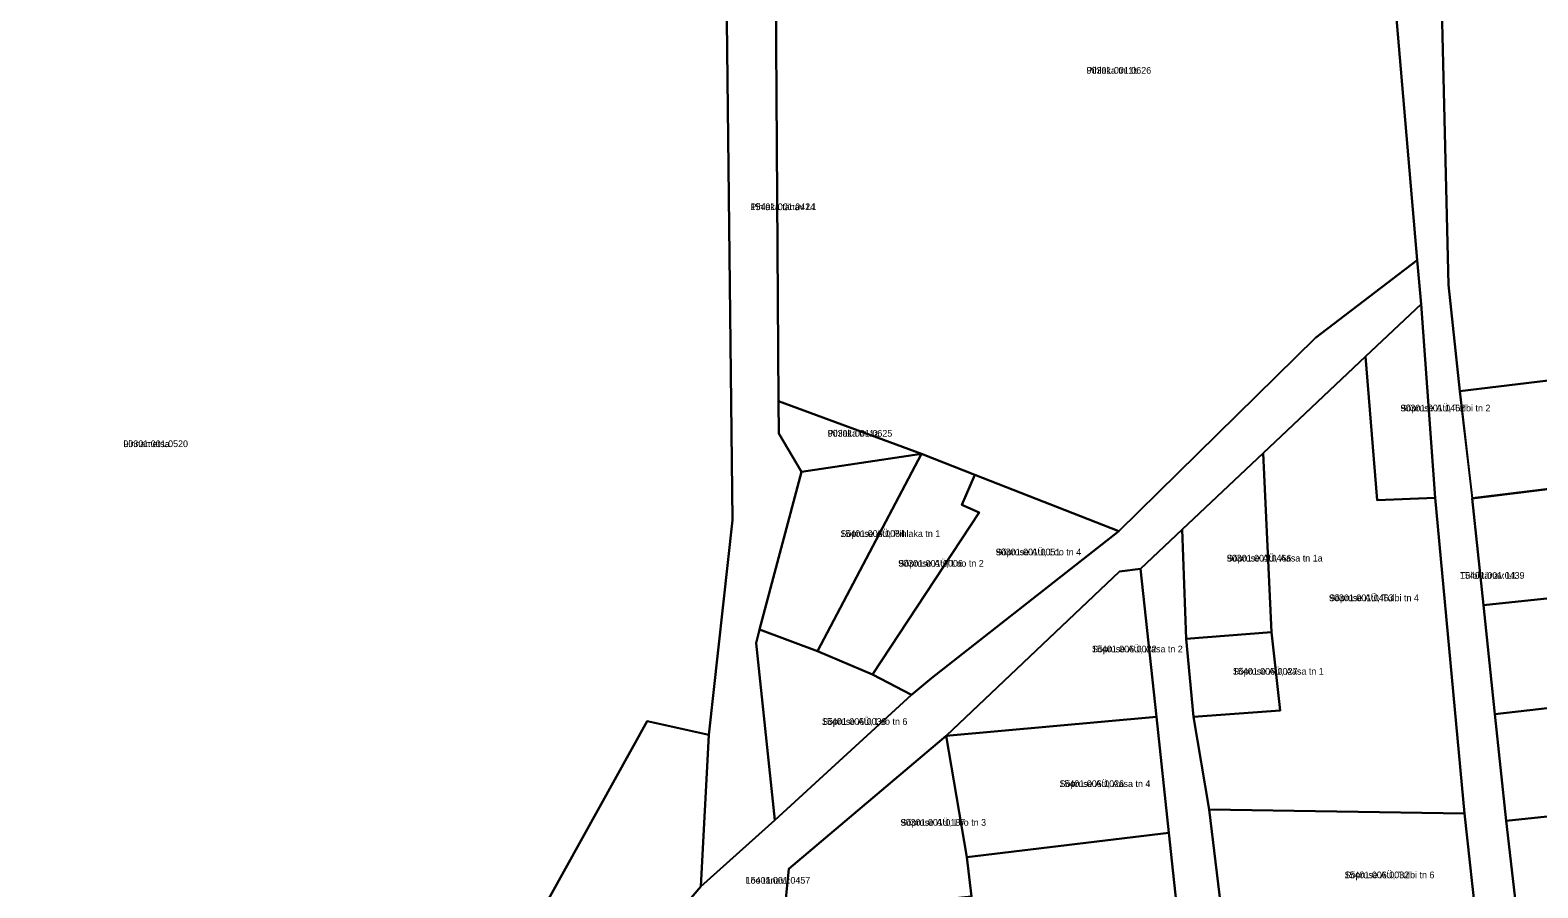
# Model space of a CAD drawing. Extents: x 634518 to 667988, y 6584667 to 6604739.
# Drawn here: x 662955.6 to 663294.1, y 6593480.9 to 6593673.3 of the extents above; entities that cross this region are included whole.
import ezdxf

# ---------------------------------------------------------------- set-up
doc = ezdxf.new("R2010")
doc.units = 0
for name, color, linetype in [('L_AADRESS', 7, 'Continuous'), ('PIIR', 7, 'Continuous'), ('TUNNUS', 7, 'Continuous')]:
    doc.layers.add(name, color=color, linetype=linetype)

msp = doc.modelspace()

# ---------------------------------------------------------------- linework, layer by layer
at = {"layer": 'PIIR'}
for points in [[(662942.12, 6593720.93), (662996.35, 6593723.15), (663060.31, 6593738.26), (663072.14, 6593752.95), (663052.3, 6593766.88), (663058.09, 6593774.85), (663073.35, 6593794.19), (663086.2, 6593810.49), (663094.98, 6593800.39), (663102.42, 6593789.23), (663105.9, 6593772.93), (663111.19, 6593748.06), (663113.31, 6593563.38), (663108.01, 6593515.2), (663094.14, 6593518.31), (663068.53, 6593472.17), (663061.55, 6593451.78), (663068.31, 6593436.61), (663032.81, 6593394.82), (662984.94, 6593349.08), (662885.24, 6593453.75)], [(663087.13, 6593458.83), (663106.19, 6593481.2), (663122.83, 6593496.08), (663153.48, 6593524.19), (663157.97, 6593527.94), (663200.02, 6593560.96), (663244.18, 6593604.26), (663267.01, 6593621.68), (663267.89, 6593611.85), (663255.42, 6593600.11), (663232.41, 6593578.44), (663214.22, 6593561.32), (663204.87, 6593552.51), (663200.17, 6593551.84), (663161.28, 6593514.98), (663125.91, 6593485.18), (663124.88, 6593474.7)], [(663213.68, 6593470.96), (663211.27, 6593493.24), (663208.45, 6593519.26), (663204.87, 6593552.51), (663214.22, 6593561.32), (663215.11, 6593536.77), (663216.81, 6593519.25), (663220.28, 6593498.49), (663224.04, 6593467.64)]]:
    msp.add_lwpolyline(points, dxfattribs=at)
for points in [[(663267.01, 6593621.68), (663244.18, 6593604.26), (663200.02, 6593560.96), (663167.68, 6593573.58), (663155.72, 6593578.26), (663123.65, 6593590.05), (663122.64, 6593738.81), (663118.55, 6593774.91), (663139.13, 6593779.62), (663155.42, 6593777.48), (663214.16, 6593755.18), (663244.18, 6593745.75), (663265.61, 6593735.03), (663262.35, 6593723.45), (663260.49, 6593707.97), (663261.89, 6593681.25)], [(663111.19, 6593748.06), (663105.9, 6593772.93), (663118.55, 6593774.91), (663122.64, 6593738.81), (663123.65, 6593590.05), (663123.7, 6593582.82), (663128.76, 6593574.2), (663119.33, 6593538.87), (663118.64, 6593535.8), (663122.83, 6593496.08), (663106.19, 6593481.2), (663108.01, 6593515.2), (663113.31, 6593563.38)], [(663265.61, 6593735.03), (663271.3, 6593730.99), (663274.02, 6593616.16), (663276.57, 6593592.3), (663279.38, 6593568.24), (663281.89, 6593544.35), (663284.45, 6593519.85), (663287, 6593495.93), (663289.83, 6593471.35), (663292.72, 6593445.68), (663281.81, 6593444.95), (663280.8, 6593454.14), (663280.56, 6593471), (663277.61, 6593497.59), (663271.07, 6593568.43), (663267.89, 6593611.85), (663267.01, 6593621.68), (663261.89, 6593681.25), (663260.49, 6593707.97), (663262.35, 6593723.45)], [(663274.02, 6593616.16), (663271.3, 6593730.99), (663308.03, 6593710.59), (663312.84, 6593638.75), (663317.48, 6593597.23), (663276.57, 6593592.3)], [(663267.89, 6593611.85), (663271.07, 6593568.43), (663258, 6593567.89), (663255.42, 6593600.11)], [(663255.42, 6593600.11), (663258, 6593567.89), (663271.07, 6593568.43), (663277.61, 6593497.59), (663220.28, 6593498.49), (663216.81, 6593519.25), (663236.26, 6593520.66), (663234.29, 6593538.24), (663232.41, 6593578.44)], [(663279.41, 6593568.36), (663276.57, 6593592.3), (663317.48, 6593597.23), (663319.87, 6593573.23)], [(663128.76, 6593574.2), (663123.7, 6593582.82), (663123.65, 6593590.05), (663155.72, 6593578.26)], [(663128.76, 6593574.2), (663155.72, 6593578.26), (663132.41, 6593534.04), (663119.33, 6593538.87)], [(663132.41, 6593534.04), (663155.72, 6593578.26), (663167.68, 6593573.58), (663164.75, 6593566.82), (663168.64, 6593565.08), (663144.76, 6593528.74)], [(663214.22, 6593561.32), (663232.41, 6593578.44), (663234.29, 6593538.24), (663215.11, 6593536.77)], [(663167.68, 6593573.58), (663200.02, 6593560.96), (663157.97, 6593527.94), (663153.48, 6593524.19), (663144.76, 6593528.74), (663168.64, 6593565.08), (663164.75, 6593566.82)], [(663281.89, 6593544.35), (663279.38, 6593568.24), (663319.87, 6593573.23), (663323.77, 6593548.72)], [(663200.17, 6593551.84), (663204.87, 6593552.51), (663208.45, 6593519.26), (663161.28, 6593514.98)], [(663323.77, 6593548.72), (663326.29, 6593524.63), (663284.45, 6593519.85), (663281.89, 6593544.35)], [(663119.33, 6593538.87), (663132.41, 6593534.04), (663144.76, 6593528.74), (663153.48, 6593524.19), (663122.83, 6593496.08), (663118.64, 6593535.8)], [(663215.11, 6593536.77), (663234.29, 6593538.24), (663236.26, 6593520.66), (663216.81, 6593519.25)], [(663284.45, 6593519.85), (663326.29, 6593524.63), (663328.84, 6593500.33), (663287, 6593495.93)], [(663068.53, 6593472.17), (663094.14, 6593518.31), (663108.01, 6593515.2), (663106.19, 6593481.2), (663087.13, 6593458.83), (663068.31, 6593436.61), (663061.55, 6593451.78)], [(663161.28, 6593514.98), (663208.45, 6593519.26), (663211.27, 6593493.24), (663165.91, 6593487.79)], [(663165.91, 6593487.79), (663166.96, 6593478.98), (663124.88, 6593474.7), (663125.91, 6593485.18), (663161.28, 6593514.98)], [(663328.84, 6593500.33), (663331.44, 6593475.5), (663289.83, 6593471.35), (663287, 6593495.93)], [(663224.04, 6593467.64), (663220.28, 6593498.49), (663277.61, 6593497.59), (663280.56, 6593471)], [(663165.91, 6593487.79), (663211.27, 6593493.24), (663213.68, 6593470.96), (663168.39, 6593464.38), (663166.96, 6593478.98)]]:
    msp.add_lwpolyline(points, close=True, dxfattribs=at)

# ---------------------------------------------------------------- texts
at = {"layer": 'L_AADRESS'}
for s, p in [('Pihlaka tn 1b', (663192.78, 6593663.54)), ('Pihlaka tänav L1', (663117.33, 6593632.94)), ('Sõpruse AÜ, Tulbi tn 2', (663263.25, 6593587.79)), ('Linnametsa', (662976.55, 6593579.78)), ('Pihlaka tn 1a', (663134.66, 6593582.12)), ('Sõpruse AÜ, Pihlaka tn 1', (663137.52, 6593559.63)), ('Sõpruse AÜ, Loo tn 4', (663172.39, 6593555.5)), ('Sõpruse AÜ, Loo tn 2', (663150.52, 6593552.96)), ('Sõpruse AÜ, Aasa tn 1a', (663224.25, 6593554.12)), ('Tulbi tänav L1', (663276.61, 6593550.24)), ('Sõpruse AÜ, Tulbi tn 4', (663247.21, 6593545.22)), ('Sõpruse AÜ, Aasa tn 2', (663193.98, 6593533.75)), ('Sõpruse AÜ, Aasa tn 1', (663225.62, 6593528.74)), ('Sõpruse AÜ, Loo tn 6', (663133.37, 6593517.48)), ('Sõpruse AÜ, Aasa tn 4', (663186.69, 6593503.53)), ('Sõpruse AÜ, Loo tn 3', (663151.04, 6593494.84)), ('Loo tänav', (663116.25, 6593481.85)), ('Sõpruse AÜ, Tulbi tn 6', (663250.69, 6593483.07))]:
    msp.add_text(s, height=1.5, dxfattribs=at).set_placement(p)
at = {"layer": 'TUNNUS'}
for s, p in [('90301:001:0626', (663192.78, 6593663.54)), ('15401:001:0424', (663117.33, 6593632.94)), ('90301:001:0462', (663263.25, 6593587.79)), ('90301:001:0520', (662976.55, 6593579.78)), ('90301:001:0625', (663134.66, 6593582.12)), ('15401:006:0064', (663137.52, 6593559.63)), ('90301:001:0051', (663172.39, 6593555.5)), ('90301:001:0006', (663150.52, 6593552.96)), ('90301:001:0466', (663224.25, 6593554.12)), ('15401:001:0439', (663276.61, 6593550.24)), ('90301:001:0463', (663247.21, 6593545.22)), ('15401:006:0022', (663193.98, 6593533.75)), ('15401:006:0027', (663225.62, 6593528.74)), ('15401:006:0039', (663133.37, 6593517.48)), ('15401:006:0026', (663186.69, 6593503.53)), ('90301:001:0187', (663151.04, 6593494.84)), ('15401:001:0457', (663116.25, 6593481.85)), ('15401:006:0032', (663250.69, 6593483.07))]:
    msp.add_text(s, height=1.5, dxfattribs=at).set_placement(p)

doc.saveas('drawing.dxf')
